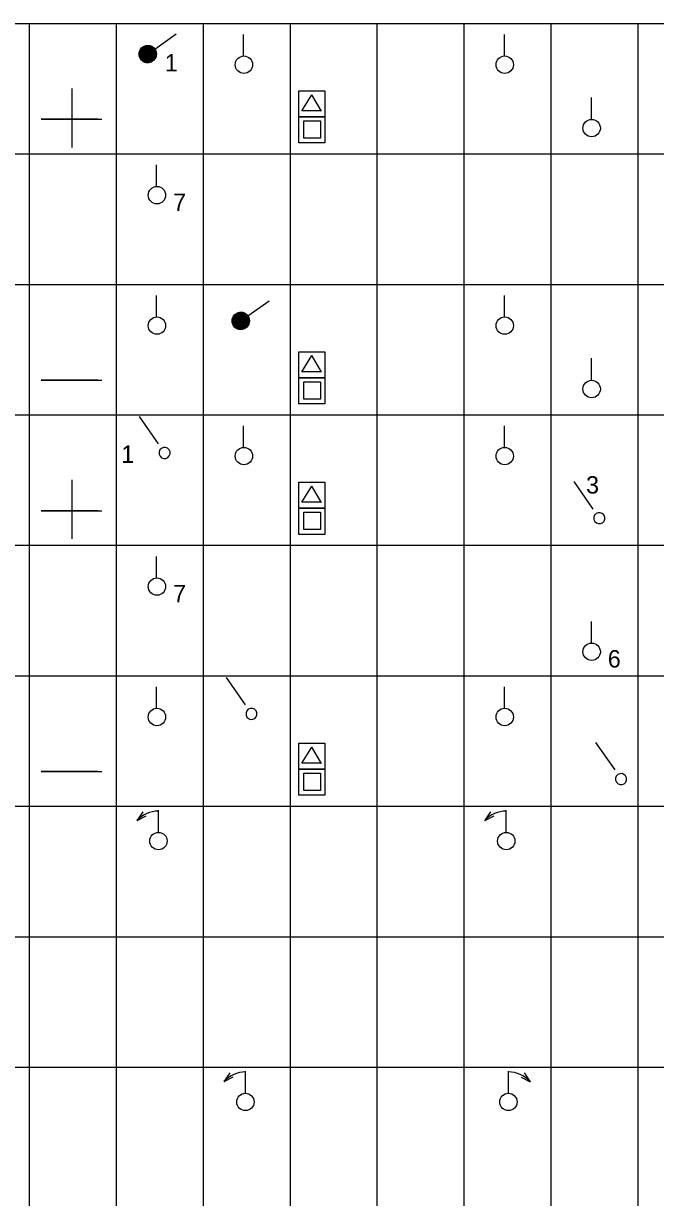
# Model space of a CAD drawing. Extents: x -28 to 822, y 61 to 665.
# Drawn here: x 192.5 to 265.2, y 246.8 to 381.7 of the extents above; entities that cross this region are included whole.
import ezdxf

# ---------------------------------------------------------------- set-up
doc = ezdxf.new("R2010")
doc.units = 0

# ---------------------------------------------------------------- blocks, each defined once
blk = doc.blocks.new('_X10')
for p, q in [((370.45, 480.11), (371.52, 481.17)), ((370.45, 480.13), (371.5, 481.17)), ((370.45, 480.14), (371.48, 481.17)), ((370.45, 480.16), (371.46, 481.17)), ((370.45, 480.18), (371.45, 481.17)), ((370.45, 480.2), (371.43, 481.17)), ((370.45, 480.21), (371.41, 481.17)), ((370.45, 480.23), (371.39, 481.17)), ((370.46, 480.06), (371.56, 481.17)), ((370.46, 480.08), (371.55, 481.17)), ((370.46, 480.09), (371.53, 481.17)), ((370.46, 480.25), (371.37, 481.17)), ((370.46, 480.27), (371.35, 481.17)), ((370.46, 480.29), (371.33, 481.17)), ((370.46, 480.01), (371.61, 481.16)), ((370.46, 480.03), (371.6, 481.16)), ((370.46, 480.04), (371.58, 481.16)), ((370.46, 480.31), (371.31, 481.16)), ((370.46, 480.33), (371.29, 481.16)), ((370.47, 480), (371.63, 481.16)), ((370.47, 480.35), (371.27, 481.16)), ((370.47, 479.97), (371.66, 481.15)), ((370.47, 479.98), (371.64, 481.15)), ((370.47, 480.37), (371.25, 481.15)), ((370.48, 479.95), (371.67, 481.15)), ((370.48, 480.4), (371.23, 481.15)), ((370.48, 479.93), (371.7, 481.14)), ((370.48, 479.94), (371.68, 481.14)), ((370.48, 480.42), (371.2, 481.14)), ((370.49, 479.91), (371.71, 481.14)), ((370.49, 479.88), (371.74, 481.13)), ((370.49, 479.9), (371.73, 481.13)), ((370.49, 480.45), (371.18, 481.13)), ((370.5, 479.87), (371.75, 481.13)), ((370.5, 480.47), (371.15, 481.13)), ((370.5, 479.86), (371.77, 481.12)), ((370.51, 479.84), (371.78, 481.12)), ((370.51, 480.5), (371.13, 481.12)), ((370.51, 479.83), (371.79, 481.11)), ((370.52, 479.82), (371.81, 481.11)), ((370.52, 480.52), (371.1, 481.11)), ((370.52, 479.81), (371.82, 481.1)), ((370.53, 479.79), (371.83, 481.1)), ((370.53, 480.55), (371.07, 481.1)), ((370.53, 479.78), (371.84, 481.09)), ((370.54, 479.77), (371.86, 481.09)), ((370.54, 479.76), (371.87, 481.08)), ((370.54, 480.58), (371.04, 481.08)), ((370.55, 479.74), (371.88, 481.08)), ((370.55, 479.73), (371.89, 481.07)), ((370.56, 480.62), (371.01, 481.07)), ((370.56, 479.72), (371.9, 481.06)), ((370.57, 479.71), (371.92, 481.06)), ((370.57, 479.7), (371.93, 481.05)), ((370.58, 479.69), (371.94, 481.05)), ((370.58, 480.66), (370.97, 481.05)), ((370.59, 479.67), (371.95, 481.04)), ((370.59, 479.66), (371.96, 481.03)), ((370.6, 479.65), (371.97, 481.03)), ((370.6, 479.64), (371.98, 481.02)), ((370.6, 480.7), (370.93, 481.02)), ((370.61, 479.63), (371.99, 481.01)), ((370.62, 479.62), (372, 481.01)), ((370.63, 479.61), (372.02, 481)), ((370.63, 479.6), (372.03, 480.99)), ((370.64, 480.75), (370.87, 480.99)), ((370.64, 479.59), (372.04, 480.98)), ((370.65, 479.58), (372.05, 480.98)), ((370.66, 479.57), (372.06, 480.97)), ((370.66, 479.56), (372.07, 480.96)), ((370.67, 479.55), (372.08, 480.95)), ((370.68, 479.54), (372.09, 480.95)), ((370.69, 479.53), (372.1, 480.94)), ((370.7, 479.52), (372.11, 480.93)), ((370.7, 479.51), (372.11, 480.92)), ((370.71, 480.84), (370.79, 480.92)), ((370.71, 479.5), (372.12, 480.91)), ((370.72, 479.49), (372.13, 480.9)), ((370.73, 479.48), (372.14, 480.9)), ((370.74, 479.47), (372.15, 480.89)), ((370.75, 479.46), (372.16, 480.88)), ((370.76, 479.46), (372.17, 480.87)), ((370.76, 479.45), (372.18, 480.86)), ((370.77, 479.44), (372.19, 480.85)), ((370.78, 479.43), (372.19, 480.84)), ((370.79, 479.42), (372.2, 480.83)), ((370.8, 479.41), (372.21, 480.82)), ((370.81, 479.4), (372.22, 480.81)), ((370.82, 479.4), (372.23, 480.8)), ((370.83, 479.39), (372.24, 480.79)), ((370.84, 479.38), (372.24, 480.78)), ((370.85, 479.37), (372.25, 480.77)), ((370.86, 479.37), (372.26, 480.76)), ((370.87, 479.36), (372.27, 480.75)), ((370.88, 479.35), (372.27, 480.74)), ((370.89, 479.34), (372.28, 480.73)), ((370.9, 479.34), (372.29, 480.72)), ((370.91, 479.33), (372.29, 480.71)), ((370.92, 479.32), (372.3, 480.7)), ((370.93, 479.32), (372.31, 480.69)), ((370.95, 479.31), (372.31, 480.68)), ((370.96, 479.3), (372.32, 480.67)), ((370.97, 479.3), (372.33, 480.66)), ((370.98, 479.29), (372.33, 480.64)), ((370.99, 479.28), (372.34, 480.63)), ((371, 479.28), (372.35, 480.62)), ((371.01, 479.27), (372.35, 480.61)), ((371.03, 479.27), (372.36, 480.6)), ((371.04, 479.26), (372.36, 480.59)), ((371.05, 479.26), (372.37, 480.57)), ((371.06, 479.25), (372.37, 480.56)), ((371.08, 479.25), (372.38, 480.55)), ((371.09, 479.24), (372.38, 480.54)), ((371.1, 479.24), (372.39, 480.52)), ((371.11, 479.23), (372.39, 480.51)), ((371.13, 479.23), (372.4, 480.5)), ((371.14, 479.22), (372.4, 480.48)), ((371.15, 479.22), (372.41, 480.47)), ((371.17, 479.21), (372.41, 480.46)), ((371.18, 479.21), (372.41, 480.44)), ((371.2, 479.21), (372.42, 480.43)), ((371.21, 479.2), (372.42, 480.42)), ((371.22, 479.2), (372.43, 480.4)), ((371.24, 479.2), (372.43, 480.39)), ((371.25, 479.19), (372.43, 480.37)), ((371.27, 479.19), (372.43, 480.36)), ((371.28, 479.19), (372.44, 480.34)), ((371.3, 479.18), (372.44, 480.33)), ((371.31, 479.18), (372.44, 480.31)), ((371.33, 479.18), (372.44, 480.3)), ((371.34, 479.18), (372.45, 480.28)), ((371.36, 479.18), (372.45, 480.26)), ((371.38, 479.17), (372.45, 480.25)), ((371.39, 479.17), (372.45, 480.23)), ((371.41, 479.17), (372.45, 480.21)), ((371.43, 479.17), (372.45, 480.2)), ((371.44, 479.17), (372.45, 480.18)), ((371.46, 479.17), (372.45, 480.16)), ((371.48, 479.17), (372.45, 480.14)), ((371.5, 479.17), (372.45, 480.13)), ((371.52, 479.17), (372.45, 480.11)), ((371.54, 479.18), (372.45, 480.09)), ((371.56, 479.18), (372.45, 480.07)), ((371.58, 479.18), (372.44, 480.05)), ((371.6, 479.18), (372.44, 480.03)), ((371.62, 479.19), (372.44, 480.01)), ((371.64, 479.19), (372.43, 479.99)), ((371.66, 479.19), (372.43, 479.96)), ((371.68, 479.2), (372.42, 479.94)), ((371.71, 479.21), (372.42, 479.92)), ((371.73, 479.21), (372.41, 479.89)), ((371.76, 479.22), (372.4, 479.87)), ((371.78, 479.23), (372.4, 479.84)), ((371.81, 479.24), (372.39, 479.81)), ((371.84, 479.25), (372.37, 479.78)), ((371.87, 479.27), (372.36, 479.75)), ((371.91, 479.28), (372.34, 479.72)), ((371.95, 479.3), (372.32, 479.68)), ((371.99, 479.33), (372.29, 479.63)), ((372.05, 479.37), (372.26, 479.58))]:
    blk.add_line(p, q)

msp = doc.modelspace()

# ---------------------------------------------------------------- linework, layer by layer
for p, q in [((5.07, 381.74), (540.62, 381.74)), ((5.07, 381.74), (293.12, 381.74)), ((5.07, 381.74), (293.12, 381.74)), ((193.12, 381.74), (193.12, 111.74)), ((203.12, 381.74), (203.12, 111.74)), ((213.12, 381.74), (213.12, 111.74)), ((223.12, 381.74), (223.12, 111.74)), ((233.12, 381.74), (233.12, 111.74)), ((243.12, 381.74), (243.12, 111.74)), ((253.12, 381.74), (253.12, 111.74)), ((263.12, 381.74), (263.12, 111.74)), ((207.57, 378.8), (210.02, 380.53)), ((217.78, 377.94), (217.78, 380.47)), ((247.78, 377.94), (247.78, 380.47)), ((198.04, 374.27), (198.04, 367.47)), ((224.46, 371.7), (225.62, 373.55)), ((226.73, 371.67), (225.62, 373.55)), ((257.81, 370.71), (257.81, 373.24)), ((226.74, 371.7), (224.46, 371.7)), ((5.07, 366.74), (292.72, 366.74)), ((207.78, 362.94), (207.78, 365.47)), ((5.07, 351.74), (540.62, 351.74)), ((207.78, 347.94), (207.78, 350.47)), ((218.27, 348.12), (220.72, 349.85)), ((247.78, 347.94), (247.78, 350.47)), ((224.46, 341.7), (225.62, 343.55)), ((226.73, 341.67), (225.62, 343.55)), ((257.81, 340.71), (257.81, 343.24)), ((226.74, 341.7), (224.46, 341.7)), ((5.07, 336.74), (540.62, 336.74)), ((5.07, 336.74), (293.12, 336.74)), ((5.07, 336.74), (293.12, 336.74)), ((205.76, 336.56), (207.96, 333.41)), ((217.78, 332.94), (217.78, 335.47)), ((247.78, 332.94), (247.78, 335.47)), ((198.04, 329.27), (198.04, 322.47)), ((224.46, 326.7), (225.62, 328.55)), ((226.73, 326.67), (225.62, 328.55)), ((255.76, 329.06), (257.96, 325.91)), ((226.74, 326.7), (224.46, 326.7)), ((5.07, 321.74), (292.72, 321.74)), ((207.78, 317.94), (207.78, 320.47)), ((257.78, 310.44), (257.78, 312.97)), ((5.07, 306.74), (540.62, 306.74)), ((215.76, 306.56), (217.96, 303.41)), ((207.78, 302.94), (207.78, 305.47)), ((247.78, 302.94), (247.78, 305.47)), ((224.46, 296.7), (225.62, 298.55)), ((226.73, 296.67), (225.62, 298.55)), ((258.26, 299.06), (260.46, 295.91)), ((226.74, 296.7), (224.46, 296.7)), ((5.07, 291.74), (540.62, 291.74)), ((206.19, 291.08), (205.5, 290.06)), ((206.55, 290.61), (205.5, 290.06)), ((207.99, 288.74), (207.99, 291.28)), ((246.19, 291.08), (245.5, 290.06)), ((246.55, 290.61), (245.5, 290.06)), ((247.99, 288.74), (247.99, 291.28)), ((5.07, 276.74), (292.72, 276.74)), ((5.07, 261.74), (540.62, 261.74)), ((216.19, 261.08), (215.5, 260.06)), ((216.55, 260.61), (215.5, 260.06)), ((217.99, 258.74), (217.99, 261.28)), ((248.24, 258.74), (248.24, 261.28)), ((249.69, 260.61), (250.73, 260.06)), ((250.04, 261.08), (250.73, 260.06))]:
    msp.add_line(p, q)
for points in [[(227.14, 371), (224.14, 371), (224.14, 374), (227.14, 374)], [(227.14, 368), (224.14, 368), (224.14, 371), (227.14, 371)], [(226.62, 368.54), (224.69, 368.54), (224.69, 370.54), (226.62, 370.54)], [(227.14, 341), (224.14, 341), (224.14, 344), (227.14, 344)], [(227.14, 338), (224.14, 338), (224.14, 341), (227.14, 341)], [(226.62, 338.54), (224.69, 338.54), (224.69, 340.54), (226.62, 340.54)], [(227.14, 326), (224.14, 326), (224.14, 329), (227.14, 329)], [(227.14, 323), (224.14, 323), (224.14, 326), (227.14, 326)], [(226.62, 323.54), (224.69, 323.54), (224.69, 325.54), (226.62, 325.54)], [(227.14, 296), (224.14, 296), (224.14, 299), (227.14, 299)], [(227.14, 293), (224.14, 293), (224.14, 296), (227.14, 296)], [(226.62, 293.54), (224.69, 293.54), (224.69, 295.54), (226.62, 295.54)]]:
    msp.add_lwpolyline(points, close=True)
for points in [[(195.44, 370.72), (201.04, 370.72), (194.5, 370.72), (201.46, 370.72)], [(195.44, 340.72), (201.04, 340.72), (194.5, 340.72), (201.46, 340.72)], [(195.44, 325.72), (201.04, 325.72), (194.5, 325.72), (201.46, 325.72)], [(195.44, 295.72), (201.04, 295.72), (194.5, 295.72), (201.46, 295.72)]]:
    msp.add_lwpolyline(points)
for centre in [(206.75, 378.22), (217.81, 377), (247.81, 377), (257.81, 369.71), (207.81, 362), (217.45, 347.54), (207.81, 347), (247.81, 347), (257.81, 339.71), (217.81, 332), (247.81, 332), (207.81, 317), (257.81, 309.5), (207.81, 302), (247.81, 302), (207.99, 287.74), (247.99, 287.74), (217.99, 257.74), (248.24, 257.74)]:
    msp.add_circle(centre, 1)
for centre, radius, start, end in [((208.69, 332.36), 0.64, 35, 215), ((208.69, 332.36), 0.64, 215, 35), ((258.69, 324.86), 0.64, 35, 215), ((258.69, 324.86), 0.64, 215, 35), ((218.69, 302.36), 0.64, 35, 215), ((218.69, 302.36), 0.64, 215, 35), ((261.19, 294.86), 0.64, 35, 215), ((261.19, 294.86), 0.64, 215, 35), ((208, 287.83), 3.36, 90.1056, 137.6031), ((248, 287.83), 3.36, 90.1056, 137.6031), ((218, 257.83), 3.36, 90.1056, 137.6031), ((248.23, 257.83), 3.36, 42.3969, 89.8944)]:
    msp.add_arc(centre, radius, start, end)

# ---------------------------------------------------------------- block references
at = {"rotation": -92.29148628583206}
for p in [(-258.18, 768.57), (-247.49, 737.9)]:
    msp.add_blockref('_X10', p, dxfattribs=at)

# ---------------------------------------------------------------- texts
for s, p in [('1', (208.71, 376.22)), ('7', (209.67, 360.19)), ('1', (203.71, 331.22)), ('3', (257.17, 327.69)), ('7', (209.67, 315.19)), ('6', (259.67, 307.69))]:
    msp.add_text(s, height=2).set_placement(p)

doc.saveas('drawing.dxf')
